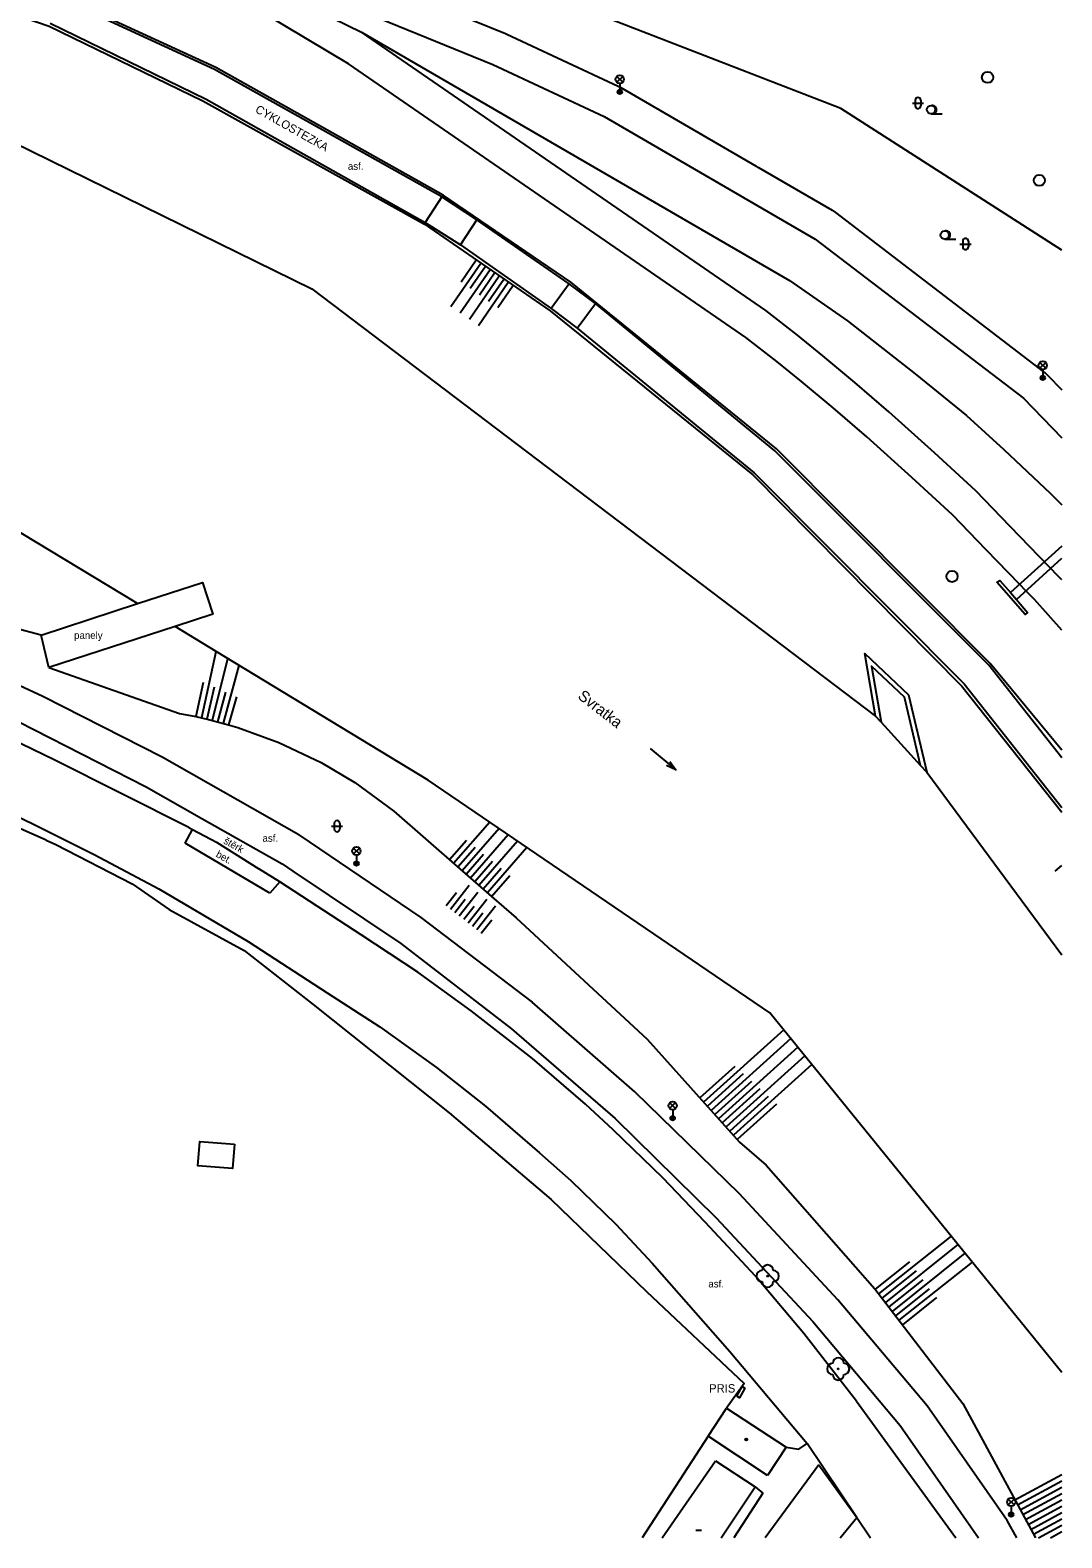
# Model space of a CAD drawing. Extents: x -598932 to -598196, y -1162207 to -1161504.
# Drawn here: x -598288 to -598195.6, y -1162207 to -1162071.8 of the extents above; entities that cross this region are included whole.
import ezdxf

# ---------------------------------------------------------------- set-up
doc = ezdxf.new("R2010")
doc.units = 0
for name, color, linetype in [('Level 22', 7, 'Continuous'), ('Level 27', 7, 'Continuous'), ('Level 33', 7, 'Continuous'), ('Level 36', 7, 'Continuous'), ('Level 39', 7, 'Continuous'), ('Level 45', 7, 'Continuous'), ('silnoproud - povrch.  znaky a  RIS  skut. velikost', 7, 'Continuous'), ('TM - budovy drevene - NP', 7, 'Continuous'), ('TM - budovy drevene - VP', 7, 'Continuous'), ('TM - budovy kovove - VP', 7, 'Continuous'), ('TM - CD - osa koleji', 7, 'Continuous'), ('TM - chodniky - VP', 7, 'Continuous'), ('TM - hladina vodniho toku_ bazenu_ nadrze', 7, 'Continuous'), ('TM - horni hrana svahu', 7, 'Continuous'), ('TM - letecke snimky - pomocna linie', 7, 'Continuous'), ('TM - plot dreveny_ kovovy - VP', 7, 'Continuous'), ('TM - popis objektu', 7, 'Continuous'), ('TM - popis povrchu', 7, 'Continuous'), ('TM - popis vodnich toku a nadrzi', 7, 'Continuous'), ('TM - rozhrani ploch obecne - VP', 7, 'Continuous'), ('TM - srafovani', 7, 'Continuous'), ('TM - vjezd na pozemek', 7, 'Continuous'), ('TM - zabradli - VP', 7, 'Continuous')]:
    doc.layers.add(name, color=color, linetype=linetype)

msp = doc.modelspace()

# ---------------------------------------------------------------- linework, layer by layer
at = {"layer": 'Level 22'}
for centre in [(-598221.93, -1162183.5), (-598215.6, -1162191.82)]:
    msp.add_circle(centre, 0.05, dxfattribs=at)
for centre, start, end in [((-598222.43, -1162183.5), 90, 270), ((-598221.93, -1162183), 0, 180), ((-598221.43, -1162183.5), 270, 90), ((-598221.93, -1162184), 180, 0), ((-598216.1, -1162191.82), 90, 270), ((-598215.6, -1162191.32), 0, 180), ((-598215.1, -1162191.82), 270, 90), ((-598215.6, -1162192.32), 180, 0)]:
    msp.add_arc(centre, 0.5, start, end, dxfattribs=at)
at = {"layer": 'Level 27'}
for centre in [(-598202.22, -1162076.08), (-598197.58, -1162085.31), (-598205.4, -1162120.8)]:
    msp.add_circle(centre, 0.5, dxfattribs=at)
at = {"layer": 'Level 33'}
for p, q in [((-598235.44, -1162076.52), (-598234.91, -1162075.99)), ((-598235.44, -1162075.99), (-598234.91, -1162076.52)), ((-598235.18, -1162076.63), (-598235.18, -1162077.38)), ((-598197.53, -1162102.15), (-598197, -1162101.62)), ((-598197.53, -1162101.62), (-598197, -1162102.15)), ((-598197.27, -1162102.26), (-598197.27, -1162103.01)), ((-598259.05, -1162145.67), (-598258.52, -1162145.14)), ((-598259.05, -1162145.14), (-598258.52, -1162145.67)), ((-598258.78, -1162145.78), (-598258.78, -1162146.53)), ((-598230.71, -1162168.49), (-598230.18, -1162167.96)), ((-598230.71, -1162167.96), (-598230.18, -1162168.49)), ((-598230.44, -1162168.6), (-598230.44, -1162169.35)), ((-598200.37, -1162204.01), (-598199.84, -1162203.48)), ((-598200.37, -1162203.48), (-598199.84, -1162204.01)), ((-598200.1, -1162204.12), (-598200.1, -1162204.87))]:
    msp.add_line(p, q, dxfattribs=at)
for centre, radius in [((-598235.18, -1162076.25), 0.375), ((-598235.18, -1162077.38), 0.2), ((-598235.18, -1162077.38), 0.145), ((-598235.18, -1162077.38), 0.0876), ((-598197.27, -1162101.89), 0.375), ((-598197.27, -1162103.01), 0.2), ((-598197.27, -1162103.01), 0.145), ((-598197.27, -1162103.01), 0.0876), ((-598258.78, -1162145.41), 0.375), ((-598258.78, -1162146.53), 0.2), ((-598258.78, -1162146.53), 0.145), ((-598258.78, -1162146.53), 0.0876), ((-598230.44, -1162168.23), 0.375), ((-598230.44, -1162169.35), 0.2), ((-598230.44, -1162169.35), 0.145), ((-598230.44, -1162169.35), 0.0876), ((-598200.1, -1162203.75), 0.375), ((-598200.1, -1162204.87), 0.2), ((-598200.1, -1162204.87), 0.145), ((-598200.1, -1162204.87), 0.0876)]:
    msp.add_circle(centre, radius, dxfattribs=at)
at = {"layer": 'Level 36'}
for p, q in [((-598208.96, -1162078.38), (-598207.96, -1162078.38)), ((-598208.71, -1162078.13), (-598208.71, -1162078.63)), ((-598208.21, -1162078.13), (-598208.21, -1162078.63)), ((-598207.28, -1162079.34), (-598206.28, -1162079.34)), ((-598206.05, -1162090.59), (-598205.05, -1162090.59)), ((-598204.69, -1162091.01), (-598203.69, -1162091.01)), ((-598204.44, -1162090.76), (-598204.44, -1162091.26)), ((-598203.94, -1162090.76), (-598203.94, -1162091.26)), ((-598261.02, -1162143.18), (-598260.02, -1162143.18)), ((-598260.77, -1162142.93), (-598260.77, -1162143.43)), ((-598260.27, -1162142.93), (-598260.27, -1162143.43))]:
    msp.add_line(p, q, dxfattribs=at)
for centre in [(-598207.28, -1162078.96), (-598206.05, -1162090.21)]:
    msp.add_circle(centre, 0.375, dxfattribs=at)
for centre, radius, start, end in [((-598208.46, -1162078.13), 0.25, 0, 180), ((-598208.46, -1162078.63), 0.25, 180, 0), ((-598207.16, -1162078.96), 0.375, 260.4059, 99.5941), ((-598205.93, -1162090.21), 0.375, 260.4059, 99.5941), ((-598204.19, -1162090.76), 0.25, 0, 180), ((-598204.19, -1162091.26), 0.25, 180, 0), ((-598260.52, -1162142.93), 0.25, 0, 180), ((-598260.52, -1162143.43), 0.25, 180, 0)]:
    msp.add_arc(centre, radius, start, end, dxfattribs=at)
at = {"layer": 'Level 39'}
msp.add_line((-598228.36, -1162206.28), (-598227.86, -1162206.28), dxfattribs=at)
for radius in [0.09, 0.0398]:
    msp.add_circle((-598223.84, -1162198.14), radius, dxfattribs=at)
at = {"layer": 'Level 45'}
msp.add_line((-598232.47, -1162136.21), (-598230.16, -1162138.12), dxfattribs=at)
msp.add_lwpolyline([(-598230.69, -1162137.38), (-598230.16, -1162138.12), (-598230.98, -1162137.74)], dxfattribs=at)
at = {"layer": 'silnoproud - povrch.  znaky a  RIS  skut. velikost'}
msp.add_lwpolyline([(-598224.7, -1162194.27), (-598224.21, -1162193.4), (-598223.96, -1162193.54), (-598224.45, -1162194.41), (-598224.7, -1162194.27)], dxfattribs=at)
at = {"layer": 'TM - budovy drevene - NP'}
msp.add_lwpolyline([(-598226.08, -1162206.96), (-598223.05, -1162202.4)], dxfattribs=at)
at = {"layer": 'TM - budovy drevene - VP'}
for points in [[(-598231.37, -1162206.96), (-598226.61, -1162200.05)], [(-598226.61, -1162200.05), (-598223.05, -1162202.4)], [(-598222.37, -1162202.97), (-598224.95, -1162206.96)], [(-598223.05, -1162202.4), (-598222.37, -1162202.97)]]:
    msp.add_lwpolyline(points, dxfattribs=at)
at = {"layer": 'TM - budovy kovove - VP'}
for points in [[(-598227.27, -1162197.85), (-598225.61, -1162195.33)], [(-598225.61, -1162195.33), (-598220.27, -1162198.84)], [(-598221.93, -1162201.36), (-598227.27, -1162197.85)], [(-598220.27, -1162198.84), (-598221.93, -1162201.36)]]:
    msp.add_lwpolyline(points, dxfattribs=at)
at = {"layer": 'TM - CD - osa koleji'}
for points in [[(-598278.81, -1162062), (-598257.63, -1162070.42), (-598246.56, -1162074.92), (-598236.58, -1162079.57), (-598217.66, -1162090.58), (-598199.01, -1162104.84), (-598195.56, -1162108.39)], [(-598278.81, -1162062), (-598258.32, -1162072.02)], [(-598258.32, -1162072.02), (-598219.97, -1162094.27)], [(-598222.1, -1162096.98), (-598258.32, -1162072.02)], [(-598219.97, -1162094.27), (-598214.78, -1162097.88), (-598208.72, -1162102.63), (-598204.12, -1162106.38), (-598200.75, -1162109.42), (-598196.57, -1162113.36), (-598195.56, -1162114.38)], [(-598195.56, -1162121.12), (-598195.82, -1162120.83), (-598200.19, -1162116.32), (-598203.27, -1162113.14), (-598206.98, -1162109.71), (-598211.07, -1162106.05), (-598214.12, -1162103.41), (-598216.99, -1162101.02), (-598219.24, -1162099.19), (-598222.1, -1162096.98)]]:
    msp.add_lwpolyline(points, dxfattribs=at)
at = {"layer": 'TM - chodniky - VP'}
for points in [[(-598251.14, -1162086.79), (-598271.49, -1162075.37), (-598285.32, -1162068.97)], [(-598286.24, -1162071.23), (-598272.26, -1162078.03), (-598252.62, -1162089.07)], [(-598247.99, -1162088.84), (-598251.14, -1162086.79)], [(-598239.71, -1162094.59), (-598247.99, -1162088.84)], [(-598252.62, -1162089.07), (-598249.46, -1162091.09)], [(-598249.46, -1162091.09), (-598241.32, -1162096.8)], [(-598237.36, -1162096.35), (-598239.71, -1162094.59)], [(-598241.32, -1162096.8), (-598239, -1162098.56)], [(-598195.56, -1162137.05), (-598202.11, -1162128.75), (-598221.27, -1162109.54), (-598237.36, -1162096.35)], [(-598239, -1162098.56), (-598223.13, -1162111.51), (-598204.31, -1162130.43), (-598195.56, -1162141.5)], [(-598263.93, -1162143.96), (-598276.19, -1162137), (-598286.88, -1162131.56), (-598302.43, -1162124.35), (-598312.4, -1162119.81), (-598318.74, -1162116.87), (-598327.14, -1162113.31), (-598328.98, -1162112.58), (-598336.46, -1162109.6), (-598339.42, -1162109.11), (-598342.87, -1162109.29)], [(-598312.83, -1162122.84), (-598303.63, -1162127.1), (-598289.09, -1162133.8), (-598277.62, -1162139.65), (-598272.63, -1162142.48)], [(-598273.8, -1162143.31), (-598285.86, -1162137.25), (-598298.65, -1162131.05)], [(-598301.39, -1162136.42), (-598287.71, -1162143.01), (-598282.29, -1162145.73), (-598276.5, -1162148.81), (-598268.49, -1162153.53), (-598261.4, -1162158.11), (-598256.68, -1162161.17), (-598251.62, -1162164.81), (-598247.22, -1162168.27), (-598242.38, -1162172.46), (-598239.58, -1162174.95), (-598235.54, -1162178.85), (-598232.27, -1162182.33), (-598225.31, -1162190.25), (-598218.38, -1162198.51)], [(-598273.8, -1162143.31), (-598273.47, -1162143.48)], [(-598263.93, -1162143.96), (-598253, -1162151.36), (-598243.04, -1162158.94)], [(-598265.65, -1162148.18), (-598267.52, -1162147)], [(-598213.96, -1162194.72), (-598218.67, -1162188.64), (-598223.01, -1162183.51), (-598227.53, -1162178.67), (-598231.31, -1162174.7), (-598235.78, -1162170.39), (-598238.24, -1162168.11), (-598243.01, -1162164.01), (-598248.5, -1162159.72), (-598253.29, -1162156.26), (-598258.35, -1162152.91), (-598265.65, -1162148.18)], [(-598264.47, -1162147.21), (-598254.81, -1162153.71)], [(-598254.81, -1162153.71), (-598244.87, -1162161.35), (-598235.59, -1162169.37), (-598226.54, -1162178.27), (-598217.87, -1162187.56), (-598210.04, -1162196.89), (-598203.04, -1162206.96)], [(-598199.59, -1162206.96), (-598200.47, -1162205.41), (-598207.62, -1162195.12), (-598215.64, -1162185.62), (-598224.46, -1162176.14), (-598233.83, -1162166.99), (-598243.04, -1162158.94)]]:
    msp.add_lwpolyline(points, dxfattribs=at)
at = {"layer": 'TM - hladina vodniho toku_ bazenu_ nadrze'}
for points in [[(-598341.89, -1162058.78), (-598331.49, -1162061.28), (-598262.79, -1162095.04)], [(-598278.41, -1162123.24), (-598288.82, -1162116.92), (-598295.43, -1162112.91), (-598326.63, -1162103.19), (-598330.25, -1162100.34), (-598337.08, -1162094.96), (-598347.31, -1162093.91)], [(-598262.79, -1162095.04), (-598212.25, -1162133.32)], [(-598271.36, -1162127.53), (-598275.04, -1162125.29)], [(-598195.56, -1162192.13), (-598221.73, -1162159.92), (-598252.35, -1162139.06), (-598271.36, -1162127.53)], [(-598207.66, -1162138.34), (-598195.56, -1162154.72)]]:
    msp.add_lwpolyline(points, dxfattribs=at)
at = {"layer": 'TM - horni hrana svahu'}
for points in [[(-598287.04, -1162126.05), (-598289.51, -1162125.42), (-598295.99, -1162123.06), (-598314.32, -1162116.96), (-598321.56, -1162115.05), (-598336.31, -1162105.77), (-598342.36, -1162101.03)], [(-598286.36, -1162128.97), (-598274.64, -1162133.08), (-598273.17, -1162133.36), (-598272.03, -1162133.63), (-598270.26, -1162134.09), (-598269.41, -1162134.34), (-598265.73, -1162135.67), (-598261.94, -1162137.49), (-598258.94, -1162139.28), (-598255.44, -1162141.84), (-598246.68, -1162149.48), (-598244.46, -1162151.41), (-598232.74, -1162162.28), (-598224.44, -1162171.49), (-598222.07, -1162173.57), (-598212.32, -1162184.64), (-598204.44, -1162194.91)], [(-598204.44, -1162194.91), (-598197.93, -1162206.96)]]:
    msp.add_lwpolyline(points, dxfattribs=at)
at = {"layer": 'TM - letecke snimky - pomocna linie'}
for points in [[(-598266.29, -1162063.75), (-598259.5, -1162066.45), (-598256.51, -1162067.64), (-598245.43, -1162072.14), (-598245.29, -1162072.2), (-598235.31, -1162076.85), (-598235.08, -1162076.97), (-598222.96, -1162084.02), (-598222.76, -1162084.14), (-598216.15, -1162087.99), (-598215.84, -1162088.2), (-598197.19, -1162102.46), (-598197.08, -1162102.54), (-598196.86, -1162102.75), (-598195.56, -1162104.09)], [(-598195.56, -1162125.62), (-598198.02, -1162122.87), (-598198.78, -1162122.09), (-598199.35, -1162121.5), (-598202.34, -1162118.41), (-598205.37, -1162115.29), (-598209, -1162111.93), (-598213.05, -1162108.3), (-598216.06, -1162105.7), (-598218.9, -1162103.33), (-598220, -1162102.44), (-598221.1, -1162101.54), (-598223.87, -1162099.4), (-598259.49, -1162074.85), (-598272.76, -1162066.91)], [(-598269.71, -1162171.69), (-598269.88, -1162173.85), (-598273, -1162173.61), (-598272.83, -1162171.44), (-598269.71, -1162171.69)], [(-598213.96, -1162194.72), (-598205.05, -1162206.96)]]:
    msp.add_lwpolyline(points, dxfattribs=at)
at = {"layer": 'TM - plot dreveny_ kovovy - VP'}
for points in [[(-598215.37, -1162078.87), (-598265.83, -1162059.3)], [(-598195.56, -1162091.56), (-598215.37, -1162078.87)], [(-598286.59, -1162144.44), (-598285.71, -1162144.81), (-598278.88, -1162148.35), (-598275.58, -1162150.66), (-598268.85, -1162154.31), (-598262.66, -1162159.16), (-598250.46, -1162168.86), (-598241.34, -1162176.63), (-598232.78, -1162184.88), (-598224.04, -1162193.14), (-598225.61, -1162195.33)], [(-598227.27, -1162197.85), (-598233.18, -1162206.96)], [(-598220.27, -1162198.84), (-598219.14, -1162199), (-598218.38, -1162198.51)], [(-598213.94, -1162205.14), (-598212.7, -1162206.96)]]:
    msp.add_lwpolyline(points, dxfattribs=at)
at = {"layer": 'TM - rozhrani ploch obecne - VP'}
for points in [[(-598251.14, -1162086.79), (-598252.62, -1162089.07)], [(-598249.46, -1162091.09), (-598247.99, -1162088.84)], [(-598239.71, -1162094.59), (-598241.32, -1162096.8)], [(-598239, -1162098.56), (-598237.36, -1162096.35)], [(-598195.56, -1162118.08), (-598200.16, -1162122.24)], [(-598199.63, -1162122.86), (-598195.56, -1162119.16)], [(-598201.39, -1162121.32), (-598201.11, -1162121.18), (-598200.16, -1162122.24)], [(-598278.41, -1162123.24), (-598272.58, -1162121.35), (-598271.66, -1162124.19), (-598275.04, -1162125.29)], [(-598199.63, -1162122.86), (-598198.65, -1162124.02), (-598198.85, -1162124.21), (-598201.39, -1162121.32)], [(-598200.16, -1162122.24), (-598199.63, -1162122.86)], [(-598287.04, -1162126.05), (-598278.41, -1162123.24)], [(-598275.04, -1162125.29), (-598286.36, -1162128.97)], [(-598286.36, -1162128.97), (-598287.04, -1162126.05)], [(-598212.25, -1162133.32), (-598213.22, -1162127.72), (-598209.31, -1162131.41), (-598207.66, -1162138.34)], [(-598208.22, -1162137.73), (-598209.67, -1162131.62), (-598212.62, -1162128.83), (-598211.75, -1162133.87)], [(-598211.75, -1162133.87), (-598212.25, -1162133.32)], [(-598211.75, -1162133.87), (-598208.22, -1162137.73)], [(-598207.66, -1162138.34), (-598208.22, -1162137.73)], [(-598272.63, -1162142.48), (-598265.44, -1162146.56)], [(-598274.13, -1162144.7), (-598273.47, -1162143.48)], [(-598273.47, -1162143.48), (-598271.32, -1162144.63), (-598267.52, -1162147)], [(-598266.53, -1162149.2), (-598274.13, -1162144.7)], [(-598265.44, -1162146.56), (-598264.47, -1162147.21)], [(-598265.65, -1162148.18), (-598266.53, -1162149.2)], [(-598217.33, -1162200.41), (-598222.15, -1162206.96)], [(-598217.33, -1162200.41), (-598213.94, -1162205.14)], [(-598215.44, -1162206.96), (-598213.94, -1162205.14)]]:
    msp.add_lwpolyline(points, dxfattribs=at)
at = {"layer": 'TM - srafovani'}
for points in [[(-598250.31, -1162096.6), (-598247.63, -1162092.73)], [(-598249.41, -1162094.41), (-598248.05, -1162092.44)], [(-598249.48, -1162097.17), (-598246.81, -1162093.29)], [(-598248.66, -1162097.74), (-598245.99, -1162093.86)], [(-598248.58, -1162094.98), (-598247.22, -1162093.01)], [(-598247.76, -1162095.55), (-598246.4, -1162093.58)], [(-598246.94, -1162096.12), (-598245.58, -1162094.15)], [(-598247.84, -1162098.3), (-598245.17, -1162094.43)], [(-598246.11, -1162096.69), (-598244.75, -1162094.71)], [(-598271.37, -1162127.55), (-598272.68, -1162133.47)], [(-598270.33, -1162128.18), (-598271.7, -1162133.7)], [(-598269.33, -1162128.78), (-598270.74, -1162133.95)], [(-598272.52, -1162130.3), (-598273.17, -1162133.36)], [(-598271.52, -1162130.72), (-598272.19, -1162133.58)], [(-598270.52, -1162131.16), (-598271.22, -1162133.82)], [(-598269.54, -1162131.59), (-598270.26, -1162134.09)], [(-598246.84, -1162142.82), (-598250.07, -1162146.52)], [(-598246, -1162143.38), (-598249.31, -1162147.18)], [(-598245.17, -1162143.95), (-598248.56, -1162147.84)], [(-598248.93, -1162144.46), (-598250.44, -1162146.2)], [(-598248.15, -1162145.09), (-598249.69, -1162146.85)], [(-598244.34, -1162144.52), (-598247.81, -1162148.49)], [(-598243.51, -1162145.08), (-598247.05, -1162149.15)], [(-598247.38, -1162145.72), (-598248.94, -1162147.51)], [(-598246.6, -1162146.35), (-598248.18, -1162148.17)], [(-598196.17, -1162147.2), (-598195.56, -1162146.72)], [(-598245.82, -1162146.97), (-598247.43, -1162148.82)], [(-598246.68, -1162149.48), (-598245.04, -1162147.6)], [(-598249.82, -1162149.15), (-598250.74, -1162150.33)], [(-598248.69, -1162148.51), (-598250.35, -1162150.64)], [(-598247.9, -1162149.12), (-598249.56, -1162151.25)], [(-598249.03, -1162149.76), (-598249.95, -1162150.95)], [(-598248.24, -1162150.38), (-598249.16, -1162151.56)], [(-598247.11, -1162149.74), (-598248.77, -1162151.87)], [(-598247.45, -1162150.99), (-598248.38, -1162152.18)], [(-598246.32, -1162150.35), (-598247.98, -1162152.48)], [(-598246.66, -1162151.61), (-598247.59, -1162152.79)], [(-598220.49, -1162161.44), (-598227.67, -1162167.91)], [(-598219.86, -1162162.22), (-598227, -1162168.65)], [(-598219.23, -1162163), (-598226.33, -1162169.4)], [(-598218.6, -1162163.77), (-598225.66, -1162170.14)], [(-598224.86, -1162164.71), (-598228, -1162167.54)], [(-598224.12, -1162165.38), (-598227.33, -1162168.28)], [(-598217.97, -1162164.55), (-598224.99, -1162170.88)], [(-598223.37, -1162166.06), (-598226.66, -1162169.02)], [(-598222.63, -1162166.73), (-598225.99, -1162169.77)], [(-598221.89, -1162167.41), (-598225.32, -1162170.51)], [(-598221.14, -1162168.09), (-598224.66, -1162171.25)], [(-598205.49, -1162179.91), (-598211.99, -1162185.08)], [(-598204.87, -1162180.67), (-598211.37, -1162185.88)], [(-598204.24, -1162181.45), (-598210.76, -1162186.67)], [(-598209.2, -1162182.22), (-598212.29, -1162184.68)], [(-598208.62, -1162183.04), (-598211.68, -1162185.48)], [(-598203.6, -1162182.24), (-598210.16, -1162187.46)], [(-598208.03, -1162183.84), (-598211.07, -1162186.27)], [(-598207.44, -1162184.64), (-598210.46, -1162187.07)], [(-598206.79, -1162185.43), (-598209.85, -1162187.86)], [(-598199.77, -1162203.56), (-598195.56, -1162201.29)], [(-598199.53, -1162204), (-598195.56, -1162201.86)], [(-598199.29, -1162204.44), (-598195.56, -1162202.43)], [(-598199.06, -1162204.88), (-598195.56, -1162202.99)], [(-598198.82, -1162205.32), (-598195.56, -1162203.56)], [(-598198.58, -1162205.76), (-598195.56, -1162204.13)], [(-598198.34, -1162206.2), (-598195.56, -1162204.7)], [(-598198.11, -1162206.64), (-598195.56, -1162205.26)], [(-598197.65, -1162206.96), (-598195.56, -1162205.83)], [(-598196.59, -1162206.96), (-598195.56, -1162206.4)]]:
    msp.add_lwpolyline(points, dxfattribs=at)
at = {"layer": 'TM - vjezd na pozemek'}
for points in [[(-598286.59, -1162144.44), (-598289.43, -1162143.19)], [(-598213.94, -1162205.14), (-598218.38, -1162198.51)]]:
    msp.add_lwpolyline(points, dxfattribs=at)
at = {"layer": 'TM - zabradli - VP'}
for points in [[(-598195.56, -1162136.36), (-598201.97, -1162128.61), (-598221.13, -1162109.37), (-598239.56, -1162094.44), (-598251, -1162086.62), (-598271.39, -1162075.18), (-598285.24, -1162068.8), (-598289.35, -1162067.1)], [(-598290.79, -1162069.95), (-598286.32, -1162071.48), (-598272.55, -1162078.17), (-598252.69, -1162089.24), (-598241.43, -1162097.01), (-598223.27, -1162111.7), (-598204.51, -1162130.63), (-598195.56, -1162141.93)]]:
    msp.add_lwpolyline(points, dxfattribs=at)

# ---------------------------------------------------------------- texts
at = {"layer": 'TM - popis objektu'}
msp.add_text('CYKLOSTEZKA', height=0.75, rotation=330.59, dxfattribs=at).set_placement((-598267.92, -1162079.16))
msp.add_text('PRIS', height=0.75, dxfattribs=at).set_placement((-598227.17, -1162193.94))
at = {"layer": 'TM - popis povrchu'}
for s, p in [('asf.', (-598259.55, -1162084.36)), ('panely', (-598284.09, -1162126.4)), ('asf.', (-598267.2, -1162144.58)), ('asf.', (-598227.24, -1162184.52))]:
    msp.add_text(s, height=0.65, dxfattribs=at).set_placement(p)
for s, rotation, p in [('štěrk', 330.82, (-598270.75, -1162144.69)), ('bet.', 331.41, (-598271.44, -1162145.9))]:
    msp.add_text(s, height=0.65, rotation=rotation, dxfattribs=at).set_placement(p)
at = {"layer": 'TM - popis vodnich toku a nadrzi'}
msp.add_text('Svratka', height=1, rotation=322.34, dxfattribs=at).set_placement((-598239.02, -1162131.68))

doc.saveas('drawing.dxf')
